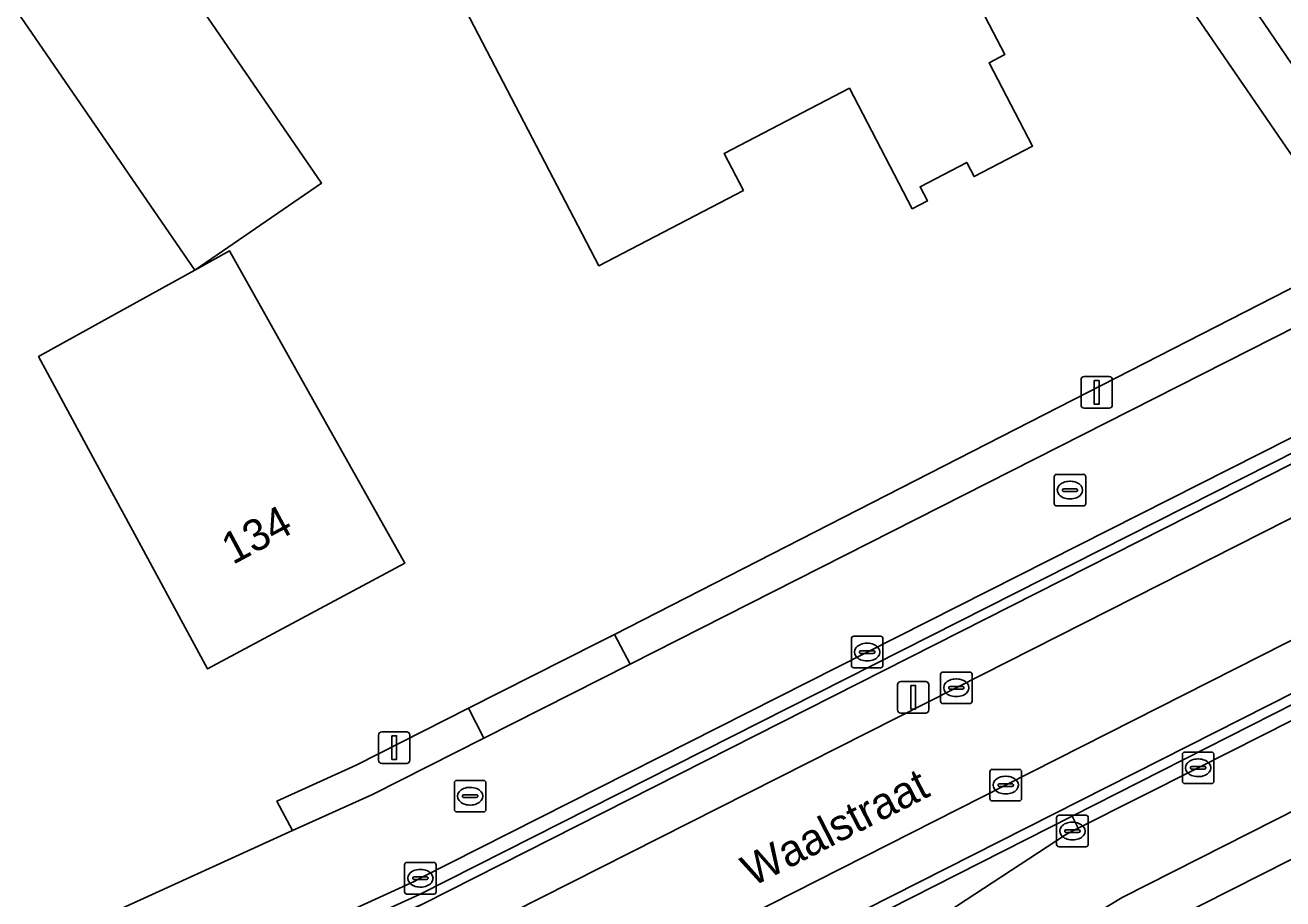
# Model space of a CAD drawing. Extents: x 157320 to 158835, y 386650 to 388491.
# Drawn here: x 157425.92 to 157465.77, y 387577.08 to 387604.77 of the extents above; entities that cross this region are included whole.
import ezdxf

# ---------------------------------------------------------------- set-up
doc = ezdxf.new("R2010")
doc.units = 0
for name, color, linetype in [('IMGEO_Berm_open', 7, 'Continuous'), ('IMGEO_Brandkraan', 7, 'Continuous'), ('IMGEO_Erf', 7, 'Continuous'), ('IMGEO_Fietspad_gesloten', 7, 'Continuous'), ('IMGEO_Groenvoorziening', 7, 'Continuous'), ('IMGEO_Kolk', 7, 'Continuous'), ('IMGEO_Lichtmast', 7, 'Continuous'), ('IMGEO_Muur', 7, 'Continuous'), ('IMGEO_Openbare_ruimte_label', 7, 'Continuous'), ('IMGEO_Pand', 7, 'Continuous'), ('IMGEO_Pand_nummerreeks', 7, 'Continuous'), ('IMGEO_Parkeervlak_open', 7, 'Continuous'), ('IMGEO_Rijbaan_lokaal_open', 7, 'Continuous'), ('IMGEO_Voetpad_open', 7, 'Continuous')]:
    doc.layers.add(name, color=color, linetype=linetype)

msp = doc.modelspace()

# ---------------------------------------------------------------- linework, layer by layer
at = {"layer": 'IMGEO_Berm_open'}
for points in [[(157470.771, 387593.59), (157470.568, 387593.961), (157468.366, 387592.876), (157467.91, 387592.639), (157452.596, 387584.902), (157438.44, 387577.734), (157438.25, 387577.629), (157429.654, 387573.707), (157429.806, 387573.314), (157438.415, 387577.215)], [(157467.056, 387583.235), (157472.011, 387585.753), (157472.185, 387585.84), (157474.156, 387586.843), (157473.956, 387587.242), (157459.097, 387579.703), (157459.289, 387579.324), (157463.083, 387581.233)]]:
    msp.add_lwpolyline(points, close=True, dxfattribs=at)
at = {"layer": 'IMGEO_Brandkraan'}
for p, q in [((157458.6, 387590.533), (157459.452, 387590.533)), ((157458.525, 387589.607), (157458.525, 387590.459)), ((157459.013, 387590.313), (157459.038, 387590.313)), ((157459.526, 387590.459), (157459.526, 387589.607)), ((157458.784, 387590.027), (157458.784, 387590.039)), ((157459.222, 387589.99), (157458.824, 387589.99)), ((157458.827, 387590.076), (157459.225, 387590.076)), ((157459.036, 387589.753), (157459.011, 387589.753)), ((157459.268, 387590.039), (157459.268, 387590.027)), ((157459.452, 387589.533), (157458.6, 387589.533)), ((157439.521, 387579.908), (157439.521, 387580.76)), ((157439.596, 387580.834), (157440.448, 387580.834)), ((157440.009, 387580.614), (157440.034, 387580.614)), ((157440.522, 387580.76), (157440.522, 387579.908)), ((157439.78, 387580.328), (157439.78, 387580.34)), ((157440.218, 387580.291), (157439.82, 387580.291)), ((157439.823, 387580.377), (157440.221, 387580.377)), ((157440.264, 387580.34), (157440.264, 387580.328)), ((157440.448, 387579.834), (157439.596, 387579.834)), ((157440.032, 387580.054), (157440.007, 387580.054))]:
    msp.add_line(p, q, dxfattribs=at)
for points in [[(157458.6, 387590.533), (157459.452, 387590.533)], [(157458.525, 387589.607), (157458.525, 387590.459)], [(157459.526, 387590.459), (157459.526, 387589.607)], [(157459.452, 387589.533), (157458.6, 387589.533)], [(157439.521, 387579.908), (157439.521, 387580.76)], [(157439.596, 387580.834), (157440.448, 387580.834)], [(157440.522, 387580.76), (157440.522, 387579.908)], [(157440.448, 387579.834), (157439.596, 387579.834)]]:
    msp.add_lwpolyline(points, dxfattribs=at)
for centre, radius, start, end in [((157458.602, 387590.457), 0.0765, 91.552, 178.448), ((157458.602, 387590.457), 0.0765, 91.552, 178.448), ((157459.45, 387590.457), 0.0765, 1.552, 88.448), ((157459.45, 387590.457), 0.0765, 1.552, 88.448), ((157458.824, 387590.036), 0.0403, 85.8775, 175.7526), ((157458.821, 387590.026), 0.0366, 178.938, 274.7102), ((157459.225, 387590.033), 0.043, 264.8664, 352.4533), ((157459.229, 387590.038), 0.0386, 1.7309, 96.639), ((157458.602, 387589.609), 0.0765, 181.552, 268.448), ((157458.602, 387589.609), 0.0765, 181.552, 268.448), ((157459.45, 387589.609), 0.0765, 271.552, 358.448), ((157459.45, 387589.609), 0.0765, 271.552, 358.448), ((157439.598, 387580.758), 0.0765, 91.552, 178.448), ((157439.598, 387580.758), 0.0765, 91.552, 178.448), ((157440.446, 387580.758), 0.0765, 1.552, 88.448), ((157440.446, 387580.758), 0.0765, 1.552, 88.448), ((157439.82, 387580.337), 0.0403, 85.8775, 175.7526), ((157439.817, 387580.327), 0.0366, 178.938, 274.7102), ((157440.221, 387580.334), 0.043, 264.8664, 352.4533), ((157440.225, 387580.339), 0.0386, 1.7309, 96.639), ((157439.598, 387579.91), 0.0765, 181.552, 268.448), ((157439.598, 387579.91), 0.0765, 181.552, 268.448), ((157440.446, 387579.91), 0.0765, 271.552, 358.448), ((157440.446, 387579.91), 0.0765, 271.552, 358.448)]:
    msp.add_arc(centre, radius, start, end, dxfattribs=at)
for centre, major_axis, ratio, start_param, end_param in [((157459.012, 387590.033), (-0.387, 0.002), 0.722429, 4.712389, 7.853982), ((157459.037, 387590.033), (-0.39, 0.002), 0.717154, 1.570796, 4.712389), ((157440.008, 387580.334), (-0.387, 0.002), 0.722429, 4.712389, 7.853982), ((157440.033, 387580.334), (-0.39, 0.002), 0.717154, 1.570796, 4.712389)]:
    msp.add_ellipse(centre, major_axis=major_axis, ratio=ratio, start_param=start_param, end_param=end_param, dxfattribs=at)
at = {"layer": 'IMGEO_Erf'}
for points in [[(157429.815, 387619.613), (157431.989, 387616.204), (157436.747, 387608.743), (157431.485, 387605.33), (157435.312, 387599.761), (157431.296, 387597.002), (157422.261, 387610.151), (157426.276, 387612.911), (157424.175, 387615.967)], [(157452.343, 387612.69), (157456.96, 387603.835), (157456.464, 387603.577), (157457.841, 387600.935), (157455.987, 387599.969), (157455.753, 387600.417), (157454.275, 387599.646), (157454.508, 387599.198), (157454.029, 387598.948), (157452.039, 387602.766), (157448.069, 387600.696), (157448.678, 387599.528), (157444.103, 387597.142), (157439.49, 387605.989)], [(157431.296, 387597.002), (157432.397, 387597.611), (157435.431, 387592.204), (157437.953, 387587.722), (157431.7, 387584.365), (157429.321, 387588.764), (157428.143, 387590.942), (157426.346, 387594.264), (157429.653, 387596.093)], [(157489.504, 387580.154), (157485.892, 387588.103), (157485.789, 387588.051), (157485.69, 387588.242), (157478.875, 387584.813), (157476.738, 387583.733), (157476.239, 387583.497), (157475.415, 387583.071), (157459.432, 387574.995), (157458.953, 387574.71), (157464.773, 387562.506), (157473.594, 387545.224), (157492.088, 387553.929), (157499.149, 387557.253), (157498.521, 387559.147)]]:
    msp.add_lwpolyline(points, close=True, dxfattribs=at)
msp.add_lwpolyline([(157414.095, 387566.194), (157429.806, 387573.314), (157429.654, 387573.707), (157428.415, 387576.527), (157428.741, 387576.675), (157434.392, 387579.243), (157433.897, 387580.178), (157436.414, 387581.319), (157439.973, 387583.126), (157444.069, 387585.194), (157444.6, 387585.462), (157468.188, 387597.53), (157456.697, 387614.284)], dxfattribs=at)
at = {"layer": 'IMGEO_Fietspad_gesloten'}
msp.add_lwpolyline([(157418.265, 387561.069), (157435.385, 387569.732), (157456.986, 387580.686), (157473.14, 387588.869), (157472.349, 387590.404), (157471.557, 387591.939), (157455.422, 387583.768), (157433.825, 387572.851), (157416.027, 387563.82)], close=True, dxfattribs=at)
at = {"layer": 'IMGEO_Groenvoorziening'}
msp.add_lwpolyline([(157429.276, 387559.732), (157458.882, 387579.113), (157459.1, 387579.229), (157459.289, 387579.324), (157459.097, 387579.703), (157441.648, 387570.849), (157420.115, 387558.795), (157422.278, 387556.137), (157426.43, 387552.461), (157431.889, 387547.783), (157434.731, 387549.184), (157431.648, 387555.145)], close=True, dxfattribs=at)
at = {"layer": 'IMGEO_Kolk'}
for p, q in [((157452.174, 387585.401), (157453.026, 387585.401)), ((157452.099, 387584.475), (157452.099, 387585.327)), ((157452.401, 387584.944), (157452.799, 387584.944)), ((157452.587, 387585.181), (157452.612, 387585.181)), ((157453.1, 387585.327), (157453.1, 387584.475)), ((157452.358, 387584.895), (157452.358, 387584.907)), ((157452.796, 387584.858), (157452.398, 387584.858)), ((157452.61, 387584.621), (157452.585, 387584.621)), ((157452.842, 387584.907), (157452.842, 387584.895)), ((157453.026, 387584.401), (157452.174, 387584.401)), ((157454.924, 387583.343), (157454.924, 387584.195)), ((157454.999, 387584.269), (157455.851, 387584.269)), ((157455.925, 387584.195), (157455.925, 387583.343)), ((157455.183, 387583.763), (157455.183, 387583.775)), ((157455.226, 387583.812), (157455.624, 387583.812)), ((157455.412, 387584.049), (157455.437, 387584.049)), ((157455.667, 387583.775), (157455.667, 387583.763)), ((157455.621, 387583.726), (157455.223, 387583.726)), ((157455.435, 387583.489), (157455.41, 387583.489)), ((157455.851, 387583.269), (157454.999, 387583.269)), ((157462.586, 387580.808), (157462.586, 387581.66)), ((157462.661, 387581.734), (157463.513, 387581.734)), ((157463.074, 387581.514), (157463.099, 387581.514)), ((157463.587, 387581.66), (157463.587, 387580.808)), ((157456.49, 387580.259), (157456.49, 387581.111)), ((157456.565, 387581.185), (157457.417, 387581.185)), ((157456.978, 387580.965), (157457.003, 387580.965)), ((157457.491, 387581.111), (157457.491, 387580.259)), ((157462.845, 387581.228), (157462.845, 387581.24)), ((157463.283, 387581.191), (157462.885, 387581.191)), ((157462.888, 387581.277), (157463.286, 387581.277)), ((157463.329, 387581.24), (157463.329, 387581.228)), ((157456.749, 387580.679), (157456.749, 387580.691)), ((157457.187, 387580.642), (157456.789, 387580.642)), ((157456.792, 387580.728), (157457.19, 387580.728)), ((157457.233, 387580.691), (157457.233, 387580.679)), ((157463.513, 387580.734), (157462.661, 387580.734)), ((157463.097, 387580.954), (157463.072, 387580.954)), ((157457.417, 387580.185), (157456.565, 387580.185)), ((157457.001, 387580.405), (157456.976, 387580.405)), ((157458.603, 387578.804), (157458.603, 387579.656)), ((157458.678, 387579.73), (157459.53, 387579.73)), ((157459.091, 387579.51), (157459.116, 387579.51)), ((157459.604, 387579.656), (157459.604, 387578.804)), ((157458.862, 387579.224), (157458.862, 387579.236)), ((157459.3, 387579.187), (157458.902, 387579.187)), ((157458.905, 387579.273), (157459.303, 387579.273)), ((157459.346, 387579.236), (157459.346, 387579.224)), ((157459.53, 387578.73), (157458.678, 387578.73)), ((157459.114, 387578.95), (157459.089, 387578.95)), ((157438.019, 387578.234), (157438.871, 387578.234)), ((157437.944, 387577.308), (157437.944, 387578.16)), ((157438.246, 387577.777), (157438.644, 387577.777)), ((157438.432, 387578.014), (157438.457, 387578.014)), ((157438.945, 387578.16), (157438.945, 387577.308)), ((157438.203, 387577.728), (157438.203, 387577.74)), ((157438.641, 387577.691), (157438.243, 387577.691)), ((157438.455, 387577.454), (157438.43, 387577.454)), ((157438.687, 387577.74), (157438.687, 387577.728)), ((157438.871, 387577.234), (157438.019, 387577.234))]:
    msp.add_line(p, q, dxfattribs=at)
for points in [[(157452.174, 387585.401), (157453.026, 387585.401)], [(157452.099, 387584.475), (157452.099, 387585.327)], [(157453.1, 387585.327), (157453.1, 387584.475)], [(157453.026, 387584.401), (157452.174, 387584.401)], [(157454.924, 387583.343), (157454.924, 387584.195)], [(157454.999, 387584.269), (157455.851, 387584.269)], [(157455.925, 387584.195), (157455.925, 387583.343)], [(157455.851, 387583.269), (157454.999, 387583.269)], [(157462.586, 387580.808), (157462.586, 387581.66)], [(157462.661, 387581.734), (157463.513, 387581.734)], [(157463.587, 387581.66), (157463.587, 387580.808)], [(157456.49, 387580.259), (157456.49, 387581.111)], [(157456.565, 387581.185), (157457.417, 387581.185)], [(157457.491, 387581.111), (157457.491, 387580.259)], [(157463.513, 387580.734), (157462.661, 387580.734)], [(157457.417, 387580.185), (157456.565, 387580.185)], [(157458.603, 387578.804), (157458.603, 387579.656)], [(157458.678, 387579.73), (157459.53, 387579.73)], [(157459.604, 387579.656), (157459.604, 387578.804)], [(157459.53, 387578.73), (157458.678, 387578.73)], [(157438.019, 387578.234), (157438.871, 387578.234)], [(157437.944, 387577.308), (157437.944, 387578.16)], [(157438.945, 387578.16), (157438.945, 387577.308)], [(157438.871, 387577.234), (157438.019, 387577.234)]]:
    msp.add_lwpolyline(points, dxfattribs=at)
for centre, radius, start, end in [((157452.176, 387585.325), 0.0765, 91.552, 178.448), ((157452.176, 387585.325), 0.0765, 91.552, 178.448), ((157453.024, 387585.325), 0.0765, 1.552, 88.448), ((157453.024, 387585.325), 0.0765, 1.552, 88.448), ((157452.398, 387584.904), 0.0403, 85.8775, 175.7526), ((157452.803, 387584.906), 0.0386, 1.7309, 96.639), ((157452.395, 387584.894), 0.0366, 178.938, 274.7102), ((157452.799, 387584.901), 0.043, 264.8664, 352.4533), ((157452.176, 387584.477), 0.0765, 181.552, 268.448), ((157452.176, 387584.477), 0.0765, 181.552, 268.448), ((157453.024, 387584.477), 0.0765, 271.552, 358.448), ((157453.024, 387584.477), 0.0765, 271.552, 358.448), ((157455.001, 387584.193), 0.0765, 91.552, 178.448), ((157455.001, 387584.193), 0.0765, 91.552, 178.448), ((157455.849, 387584.193), 0.0765, 1.552, 88.448), ((157455.849, 387584.193), 0.0765, 1.552, 88.448), ((157455.223, 387583.772), 0.0403, 85.8775, 175.7526), ((157455.22, 387583.762), 0.0366, 178.938, 274.7102), ((157455.624, 387583.769), 0.043, 264.8664, 352.4533), ((157455.628, 387583.774), 0.0386, 1.7309, 96.639), ((157455.001, 387583.345), 0.0765, 181.552, 268.448), ((157455.001, 387583.345), 0.0765, 181.552, 268.448), ((157455.849, 387583.345), 0.0765, 271.552, 358.448), ((157455.849, 387583.345), 0.0765, 271.552, 358.448), ((157462.663, 387581.658), 0.0765, 91.552, 178.448), ((157462.663, 387581.658), 0.0765, 91.552, 178.448), ((157463.511, 387581.658), 0.0765, 1.552, 88.448), ((157463.511, 387581.658), 0.0765, 1.552, 88.448), ((157456.567, 387581.109), 0.0765, 91.552, 178.448), ((157456.567, 387581.109), 0.0765, 91.552, 178.448), ((157457.415, 387581.109), 0.0765, 1.552, 88.448), ((157457.415, 387581.109), 0.0765, 1.552, 88.448), ((157462.885, 387581.237), 0.0403, 85.8775, 175.7526), ((157462.882, 387581.227), 0.0366, 178.938, 274.7102), ((157463.286, 387581.234), 0.043, 264.8664, 352.4533), ((157463.29, 387581.239), 0.0386, 1.7309, 96.639), ((157456.789, 387580.688), 0.0403, 85.8775, 175.7526), ((157456.786, 387580.678), 0.0366, 178.938, 274.7102), ((157457.19, 387580.685), 0.043, 264.8664, 352.4533), ((157457.194, 387580.69), 0.0386, 1.7309, 96.639), ((157462.663, 387580.81), 0.0765, 181.552, 268.448), ((157462.663, 387580.81), 0.0765, 181.552, 268.448), ((157463.511, 387580.81), 0.0765, 271.552, 358.448), ((157463.511, 387580.81), 0.0765, 271.552, 358.448), ((157456.567, 387580.261), 0.0765, 181.552, 268.448), ((157456.567, 387580.261), 0.0765, 181.552, 268.448), ((157457.415, 387580.261), 0.0765, 271.552, 358.448), ((157457.415, 387580.261), 0.0765, 271.552, 358.448), ((157458.68, 387579.654), 0.0765, 91.552, 178.448), ((157458.68, 387579.654), 0.0765, 91.552, 178.448), ((157459.528, 387579.654), 0.0765, 1.552, 88.448), ((157459.528, 387579.654), 0.0765, 1.552, 88.448), ((157458.902, 387579.233), 0.0403, 85.8775, 175.7526), ((157458.899, 387579.223), 0.0366, 178.938, 274.7102), ((157459.303, 387579.23), 0.043, 264.8664, 352.4533), ((157459.307, 387579.235), 0.0386, 1.7309, 96.639), ((157458.68, 387578.806), 0.0765, 181.552, 268.448), ((157458.68, 387578.806), 0.0765, 181.552, 268.448), ((157459.528, 387578.806), 0.0765, 271.552, 358.448), ((157459.528, 387578.806), 0.0765, 271.552, 358.448), ((157438.021, 387578.158), 0.0765, 91.552, 178.448), ((157438.021, 387578.158), 0.0765, 91.552, 178.448), ((157438.869, 387578.158), 0.0765, 1.552, 88.448), ((157438.869, 387578.158), 0.0765, 1.552, 88.448), ((157438.243, 387577.737), 0.0403, 85.8775, 175.7526), ((157438.648, 387577.739), 0.0386, 1.7309, 96.639), ((157438.24, 387577.727), 0.0366, 178.938, 274.7102), ((157438.644, 387577.734), 0.043, 264.8664, 352.4533), ((157438.021, 387577.31), 0.0765, 181.552, 268.448), ((157438.021, 387577.31), 0.0765, 181.552, 268.448), ((157438.869, 387577.31), 0.0765, 271.552, 358.448), ((157438.869, 387577.31), 0.0765, 271.552, 358.448)]:
    msp.add_arc(centre, radius, start, end, dxfattribs=at)
for centre, major_axis, ratio, start_param, end_param in [((157452.586, 387584.901), (-0.387, 0.002), 0.722429, 4.712389, 7.853982), ((157452.611, 387584.901), (-0.39, 0.002), 0.717154, 1.570796, 4.712389), ((157455.411, 387583.769), (-0.387, 0.002), 0.722429, 4.712389, 7.853982), ((157455.436, 387583.769), (-0.39, 0.002), 0.717154, 1.570796, 4.712389), ((157463.073, 387581.234), (-0.387, 0.002), 0.722429, 4.712389, 7.853982), ((157463.098, 387581.234), (-0.39, 0.002), 0.717154, 1.570796, 4.712389), ((157456.977, 387580.685), (-0.387, 0.002), 0.722429, 4.712389, 7.853982), ((157457.002, 387580.685), (-0.39, 0.002), 0.717154, 1.570796, 4.712389), ((157459.09, 387579.23), (-0.387, 0.002), 0.722429, 4.712389, 7.853982), ((157459.115, 387579.23), (-0.39, 0.002), 0.717154, 1.570796, 4.712389), ((157438.431, 387577.734), (-0.387, 0.002), 0.722429, 4.712389, 7.853982), ((157438.456, 387577.734), (-0.39, 0.002), 0.717154, 1.570796, 4.712389)]:
    msp.add_ellipse(centre, major_axis=major_axis, ratio=ratio, start_param=start_param, end_param=end_param, dxfattribs=at)
at = {"layer": 'IMGEO_Lichtmast'}
for p, q in [((157459.376, 387592.731), (157459.376, 387593.531)), ((157459.376, 387593.531), (157459.376, 387592.731)), ((157459.476, 387593.631), (157460.266, 387593.631)), ((157460.266, 387593.631), (157459.476, 387593.631)), ((157460.366, 387593.531), (157460.366, 387592.731)), ((157460.366, 387592.731), (157460.366, 387593.531)), ((157460.266, 387592.631), (157459.476, 387592.631)), ((157459.476, 387592.631), (157460.266, 387592.631)), ((157453.564, 387583.07), (157453.564, 387583.87)), ((157453.564, 387583.87), (157453.564, 387583.07)), ((157453.664, 387583.97), (157454.454, 387583.97)), ((157454.454, 387583.97), (157453.664, 387583.97)), ((157454.554, 387583.87), (157454.554, 387583.07)), ((157454.554, 387583.07), (157454.554, 387583.87)), ((157454.454, 387582.97), (157453.664, 387582.97)), ((157453.664, 387582.97), (157454.454, 387582.97)), ((157437.123, 387581.472), (157437.123, 387582.272)), ((157437.123, 387582.272), (157437.123, 387581.472)), ((157437.223, 387582.372), (157438.013, 387582.372)), ((157438.013, 387582.372), (157437.223, 387582.372)), ((157438.113, 387582.272), (157438.113, 387581.472)), ((157438.113, 387581.472), (157438.113, 387582.272)), ((157438.013, 387581.372), (157437.223, 387581.372)), ((157437.223, 387581.372), (157438.013, 387581.372))]:
    msp.add_line(p, q, dxfattribs=at)
for points in [[(157459.796, 387593.506), (157459.946, 387593.506), (157459.946, 387592.756), (157459.796, 387592.756), (157459.796, 387593.506)], [(157453.984, 387583.845), (157454.134, 387583.845), (157454.134, 387583.095), (157453.984, 387583.095), (157453.984, 387583.845)], [(157437.543, 387582.247), (157437.693, 387582.247), (157437.693, 387581.497), (157437.543, 387581.497), (157437.543, 387582.247)]]:
    msp.add_lwpolyline(points, dxfattribs=at)
for centre, start, end in [((157459.476, 387593.531), 90, 180), ((157459.476, 387593.531), 90, 180), ((157460.266, 387593.531), 0, 90), ((157460.266, 387593.531), 360, 90), ((157459.476, 387592.731), 180, 270), ((157459.476, 387592.731), 180, 270), ((157460.266, 387592.731), 270, 0), ((157460.266, 387592.731), 270, 0), ((157453.664, 387583.87), 90, 180), ((157453.664, 387583.87), 90, 180), ((157454.454, 387583.87), 0, 90), ((157454.454, 387583.87), 360, 90), ((157453.664, 387583.07), 180, 270), ((157453.664, 387583.07), 180, 270), ((157454.454, 387583.07), 270, 0), ((157454.454, 387583.07), 270, 0), ((157437.223, 387582.272), 90, 180), ((157437.223, 387582.272), 90, 180), ((157438.013, 387582.272), 0, 90), ((157438.013, 387582.272), 360, 90), ((157437.223, 387581.472), 180, 270), ((157437.223, 387581.472), 180, 270), ((157438.013, 387581.472), 270, 0), ((157438.013, 387581.472), 270, 0)]:
    msp.add_arc(centre, 0.1, start, end, dxfattribs=at)
at = {"layer": 'IMGEO_Muur'}
for points in [[(157438.555, 387576.929), (157470.913, 387593.326), (157470.771, 387593.59), (157438.415, 387577.215), (157429.806, 387573.314), (157414.095, 387566.194), (157414.303, 387565.939)], [(157473.956, 387587.242), (157473.819, 387587.515), (157441.48, 387571.141), (157419.925, 387559.029), (157420.115, 387558.795), (157441.648, 387570.849), (157459.097, 387579.703)]]:
    msp.add_lwpolyline(points, close=True, dxfattribs=at)
at = {"layer": 'IMGEO_Pand'}
for points in [[(157426.433, 387612.682), (157426.276, 387612.911), (157422.261, 387610.151), (157431.296, 387597.002), (157435.312, 387599.761), (157431.485, 387605.33)], [(157452.039, 387602.766), (157454.029, 387598.948), (157454.508, 387599.198), (157454.275, 387599.646), (157455.753, 387600.417), (157455.987, 387599.969), (157457.841, 387600.935), (157456.464, 387603.577), (157456.96, 387603.835), (157452.343, 387612.69), (157439.49, 387605.989), (157444.103, 387597.142), (157448.678, 387599.528), (157448.069, 387600.696)], [(157435.431, 387592.204), (157432.397, 387597.611), (157431.296, 387597.002), (157429.653, 387596.093), (157426.346, 387594.264), (157428.143, 387590.942), (157429.321, 387588.764), (157431.7, 387584.365), (157437.953, 387587.722)]]:
    msp.add_lwpolyline(points, close=True, dxfattribs=at)
at = {"layer": 'IMGEO_Parkeervlak_open'}
msp.add_lwpolyline([(157459.432, 387574.995), (157475.415, 387583.071), (157476.239, 387583.497), (157476.738, 387583.733), (157475.174, 387584.46), (157460.674, 387577.122), (157458.887, 387576.036)], close=True, dxfattribs=at)
at = {"layer": 'IMGEO_Rijbaan_lokaal_open'}
for points in [[(157413.31, 387671.395), (157414.051, 387670.696), (157419.814, 387665.122), (157430.656, 387654.695), (157432.066, 387653.223), (157433.339, 387651.683), (157433.944, 387650.859), (157434.281, 387650.428), (157442.615, 387638.112), (157450.126, 387626.955), (157466.232, 387603.27), (157468.238, 387600.234), (157473.33, 387603.504), (157468.955, 387609.99)], [(157434.202, 387559.877), (157448.47, 387569.217), (157454.897, 387573.424), (157457.215, 387574.942), (157458.887, 387576.036), (157460.674, 387577.122), (157475.174, 387584.46), (157472.185, 387585.84), (157472.011, 387585.753), (157467.056, 387583.235), (157463.083, 387581.233), (157459.289, 387579.324), (157459.1, 387579.229), (157458.882, 387579.113), (157429.276, 387559.732), (157431.648, 387555.145), (157434.731, 387549.184), (157437.4, 387550.497), (157436.999, 387551.29), (157434.768, 387555.6), (157434.292, 387556.505), (157433.601, 387557.819)]]:
    msp.add_lwpolyline(points, dxfattribs=at)
msp.add_lwpolyline([(157429.654, 387573.707), (157438.25, 387577.629), (157438.44, 387577.734), (157452.596, 387584.902), (157467.91, 387592.639), (157468.366, 387592.876), (157466.982, 387595.618), (157445.088, 387584.519), (157440.46, 387582.17), (157436.923, 387580.393), (157434.392, 387579.243), (157428.741, 387576.675), (157428.415, 387576.527)], close=True, dxfattribs=at)
at = {"layer": 'IMGEO_Voetpad_open'}
for points in [[(157450.126, 387626.955), (157448.87, 387626.108), (157456.697, 387614.284), (157468.188, 387597.53), (157469.541, 387598.164), (157468.238, 387600.234), (157466.232, 387603.27)], [(157416.027, 387563.82), (157433.825, 387572.851), (157455.422, 387583.768), (157471.557, 387591.939), (157470.913, 387593.326), (157438.555, 387576.929), (157415.05, 387565.021)], [(157419.244, 387559.866), (157441.48, 387571.141), (157473.819, 387587.515), (157473.14, 387588.869), (157456.986, 387580.686), (157435.385, 387569.732), (157418.265, 387561.069)], [(157440.46, 387582.17), (157445.088, 387584.519), (157444.6, 387585.462), (157444.069, 387585.194), (157439.973, 387583.126)], [(157434.392, 387579.243), (157436.923, 387580.393), (157440.46, 387582.17), (157439.973, 387583.126), (157436.414, 387581.319), (157433.897, 387580.178)]]:
    msp.add_lwpolyline(points, close=True, dxfattribs=at)
msp.add_lwpolyline([(157469.592, 387598.084), (157469.541, 387598.164), (157468.188, 387597.53), (157444.6, 387585.462), (157445.088, 387584.519), (157466.982, 387595.618)], dxfattribs=at)

# ---------------------------------------------------------------- texts
at = {"layer": 'IMGEO_Openbare_ruimte_label'}
msp.add_text('Waalstraat', height=1, rotation=27.1288, dxfattribs=at).set_placement((157448.957, 387577.45))
at = {"layer": 'IMGEO_Pand_nummerreeks'}
msp.add_text('134', height=1, rotation=28.2296, dxfattribs=at).set_placement((157432.501, 387587.655))

doc.saveas('drawing.dxf')
